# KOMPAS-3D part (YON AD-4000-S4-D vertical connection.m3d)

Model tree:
1. Операция без истории:1
2. Операция без истории:2
3. Операция без истории:3
4. Операция без истории:4
5. Операция без истории:5
6. Операция без истории:6
7. Операция без истории:7
8. Операция без истории:8
9. Операция без истории:9
10. Операция без истории:10
11. Операция без истории:11
12. Операция без истории:12
13. Операция без истории:13
14. Операция без истории:14
15. Операция без истории:15
16. Операция без истории:16
17. Операция без истории:17
18. Операция без истории:18
19. Операция без истории:19
20. Операция без истории:20
21. Операция без истории:21
22. Операция без истории:22
23. Операция без истории:23
24. Операция без истории:24
25. Операция без истории:25
26. Операция без истории:26
27. Операция без истории:27
28. Операция без истории:28
29. Операция без истории:29
30. Операция без истории:30
31. Операция без истории:31
32. Операция без истории:32
33. Операция без истории:33
34. Операция без истории:34
35. Операция без истории:35
36. Операция без истории:36
37. Операция без истории:37
38. Операция без истории:38
39. Операция без истории:39
40. Операция без истории:40
41. Операция без истории:41
42. Операция без истории:42
43. Операция без истории:43
44. Операция без истории:44
45. Операция без истории:45
46. Операция без истории:46
47. Операция без истории:47
48. Операция без истории:48
49. Операция без истории:49
50. Операция без истории:50
51. Операция без истории:51
52. Операция без истории:52
53. Операция без истории:53
54. Операция без истории:54
55. Операция без истории:55
56. Операция без истории:56
57. Операция без истории:57
58. Операция без истории:58
59. Операция без истории:59
60. Операция без истории:60
61. Операция без истории:61
62. Операция без истории:62
63. Операция без истории:63
64. Операция без истории:64
65. Операция без истории:65
66. Операция без истории:66
67. Операция без истории:67
68. Операция без истории:68
69. Операция без истории:69
70. Операция без истории:70

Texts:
  YON AD-4000-S4-D vertical connection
